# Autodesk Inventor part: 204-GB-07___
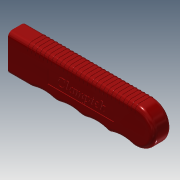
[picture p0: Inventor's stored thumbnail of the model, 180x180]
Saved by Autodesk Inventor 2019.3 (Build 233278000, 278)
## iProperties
Created: 2010-06
Part Number: 204-GB-07___
Material: Ogólny
Document SubType Name: Modeling
Designer: CADENGINEERING4
Density: 1 g/cm^3
Appearance: Domyślna
Author: CADENGINEERING4
Revision Number: ANY
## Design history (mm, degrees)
feature "NONE"
node "Bryła1"
